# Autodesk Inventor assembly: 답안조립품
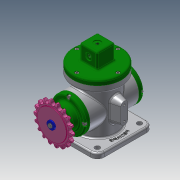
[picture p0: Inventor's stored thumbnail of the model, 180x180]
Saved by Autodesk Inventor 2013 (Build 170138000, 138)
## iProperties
Created: 2021-03
Part Number: 답안조립품
Document SubType Name: Assembly
Designer: a
Author: a
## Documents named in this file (19)
- C:\Users\a\Desktop\710306V1018\답안조립품.iam
- C:\Users\a\Desktop\710306V1018\본체.ipt
- C:\Users\a\Desktop\710306V1018\E-링.ipt
- C:\Users\a\Desktop\710306V1018\덮개.ipt
- C:\Users\a\Desktop\710306V1018\뒤커버.ipt
- C:\Users\a\Desktop\710306V1018\링크.ipt
- C:\Users\a\Desktop\710306V1018\멈춤나사 M3.ipt
- C:\Users\a\Desktop\710306V1018\베어링 17 x 40 x 12.ipt
- C:\Users\a\Desktop\710306V1018\볼트 M4 x 8.ipt
- C:\Users\a\Desktop\710306V1018\볼트 M4 x 10.ipt
- C:\Users\a\Desktop\710306V1018\스프로킷.ipt
- C:\Users\a\Desktop\710306V1018\슬라이더.ipt
- C:\Users\a\Desktop\710306V1018\앞커버.ipt
- C:\Users\a\Desktop\710306V1018\오일 실 17 30 8.ipt
- C:\Users\a\Desktop\710306V1018\와셔 4x16.ipt
- C:\Users\a\Desktop\710306V1018\클레비스 핀 6 x 22.ipt
- 클레비스 핀 6 x 22.ipt
- C:\Users\a\Desktop\710306V1018\키 4 x 4 x 12.ipt
- C:\Users\a\Desktop\710306V1018\편심축.ipt
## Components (1 placed, 1 different names)
1. E-링:1
